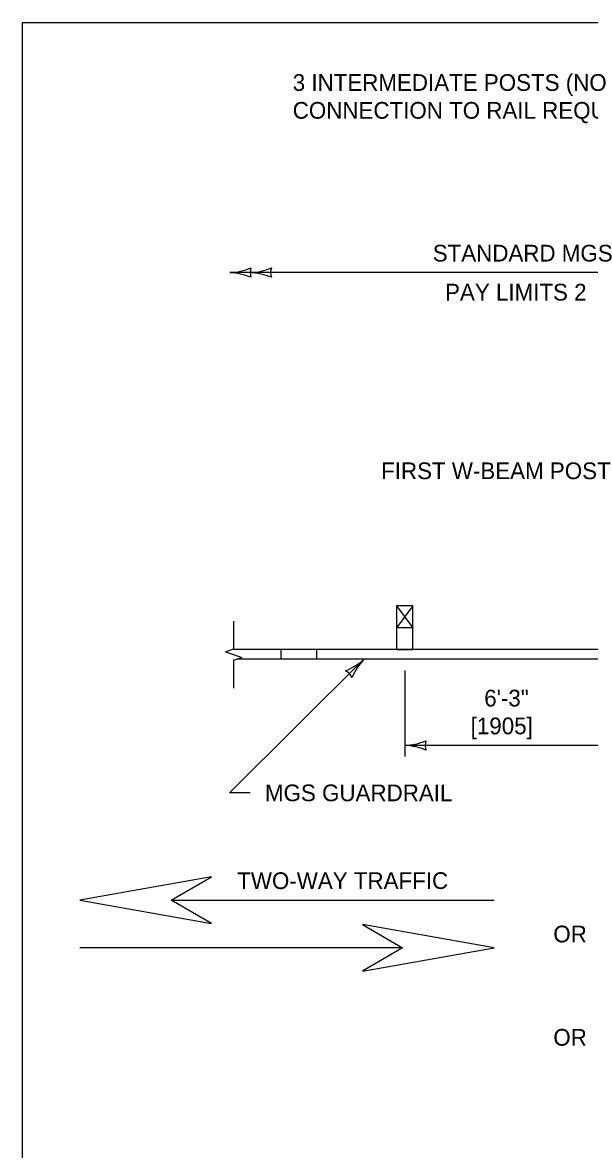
# Model space of a CAD drawing. Extents: x 49991.4 to 50021, y 49987.6 to 50011.4.
# Drawn here: x 49999.384 to 50001.42, y 49994.953 to 49998.999 of the extents above; entities that cross this region are included whole.
import ezdxf

# ---------------------------------------------------------------- set-up
doc = ezdxf.new("R2010")
doc.units = 0
for name, color, linetype in [('Level 1', 7, 'Continuous'), ('Level 2', 7, 'Continuous'), ('Level 3', 7, 'Continuous'), ('Level 6', 7, 'Continuous')]:
    doc.layers.add(name, color=color, linetype=linetype)

msp = doc.modelspace()

# ---------------------------------------------------------------- linework, layer by layer
at = {"layer": 'Level 1'}
for p, q in [((50000.7854, 49996.9044), (50000.7274, 49996.9044)), ((50000.7274, 49996.9044), (50000.7274, 49996.8264)), ((50000.7854, 49996.9044), (50000.7274, 49996.8264)), ((50000.7274, 49996.9044), (50000.7854, 49996.8264)), ((50000.7854, 49996.8264), (50000.7854, 49996.9044)), ((50000.7274, 49996.8264), (50000.7274, 49996.7484)), ((50000.7854, 49996.8264), (50000.7274, 49996.8264)), ((50000.7854, 49996.7484), (50000.7854, 49996.8264)), ((50003.8664, 49996.7484), (50000.1363, 49996.7484)), ((50000.3119, 49996.7484), (50000.3119, 49996.7132)), ((50000.4389, 49996.7484), (50000.4389, 49996.7132)), ((50000.7274, 49996.7484), (50000.7854, 49996.7484)), ((50003.9076, 49996.7132), (50000.1529, 49996.7132))]:
    msp.add_line(p, q, dxfattribs=at)
msp.add_lwpolyline([(49999.3835, 49998.9992), (50016.7501, 49998.9992), (50016.7501, 49987.7988), (49999.3835, 49987.7988)], close=True, dxfattribs=at)
at = {"layer": 'Level 3'}
for p, q in [((50002.2804, 49998.1012), (50000.1279, 49998.1012)), ((50000.6099, 49996.7132), (50000.1267, 49996.2334)), ((50000.7564, 49996.6732), (50000.7564, 49996.3637)), ((50001.5184, 49996.4037), (50000.7564, 49996.4037)), ((50000.2017, 49996.2334), (50000.1267, 49996.2334)), ((49999.9176, 49995.8483), (50001.0776, 49995.8483)), ((50000.749, 49995.6765), (49999.589, 49995.6765))]:
    msp.add_line(p, q, dxfattribs=at)
for points in [[(50000.0618, 49995.9317), (49999.589, 49995.8483), (50000.0618, 49995.7645), (49999.9176, 49995.8483)], [(50000.6048, 49995.5931), (50001.0776, 49995.6765), (50000.6048, 49995.7603), (50000.749, 49995.6765)]]:
    msp.add_lwpolyline(points, close=True, dxfattribs=at)
for centre, radius, start, end in [((50000.1187, 49998.3233), 0.2223, 272.3605, 292.544), ((50000.1922, 49998.3233), 0.2223, 272.3605, 292.544), ((50000.2561, 49998.1012), 0.0548, 162.1388, 197.8612), ((50000.3296, 49998.1012), 0.0548, 162.1388, 197.8612), ((50000.1164, 49997.8685), 0.233, 67.9228, 87.1727), ((50000.1898, 49997.8685), 0.233, 67.9228, 87.1727), ((50000.4599, 49996.8773), 0.2223, 292.2571, 312.4406), ((50000.782, 49996.5562), 0.233, 137.6284, 156.8783), ((50000.5189, 49996.6229), 0.0548, 26.9399, 62.6623), ((50000.7472, 49996.6258), 0.2223, 272.3605, 292.544), ((50000.8846, 49996.4037), 0.0548, 162.1388, 197.8612), ((50000.7449, 49996.171), 0.233, 67.9228, 87.1727)]:
    msp.add_arc(centre, radius, start, end, dxfattribs=at)
at = {"layer": 'Level 6'}
for p, q in [((50000.1419, 49996.8504), (50000.1419, 49996.7504)), ((50000.1131, 49996.7403), (50000.1419, 49996.7504)), ((50000.1131, 49996.7403), (50000.1419, 49996.7299)), ((50000.1419, 49996.7299), (50000.171, 49996.7197)), ((50000.1419, 49996.7093), (50000.171, 49996.7197)), ((50000.1419, 49996.7093), (50000.1419, 49996.6093))]:
    msp.add_line(p, q, dxfattribs=at)

# ---------------------------------------------------------------- texts
at = {"layer": 'Level 2'}
for s, rotation, p in [('3 INTERMEDIATE POSTS (NO', 360, (50000.3541, 49998.7539)), ('CONNECTION TO RAIL REQUIRED)', 360, (50000.3541, 49998.6539)), ('TWO-WAY TRAFFIC', 0.0331, (50000.1548, 49995.888))]:
    msp.add_text(s, height=0.06, rotation=rotation, dxfattribs=at).set_placement(p)
for s, p in [('STANDARD MGS', (50000.857, 49998.1412)), ('PAY LIMITS 2', (50000.9013, 49998.0012)), ('FIRST W-BEAM POST', (50000.6716, 49997.3598)), ('6\'-3"', (50001.042, 49996.5437)), ('[1905]', (50000.9933, 49996.4437)), ('MGS GUARDRAIL', (50000.2544, 49996.2034)), ('OR', (50001.2902, 49995.6967)), ('OR', (50001.2902, 49995.3257))]:
    msp.add_text(s, height=0.06, dxfattribs=at).set_placement(p)

doc.saveas('drawing.dxf')
